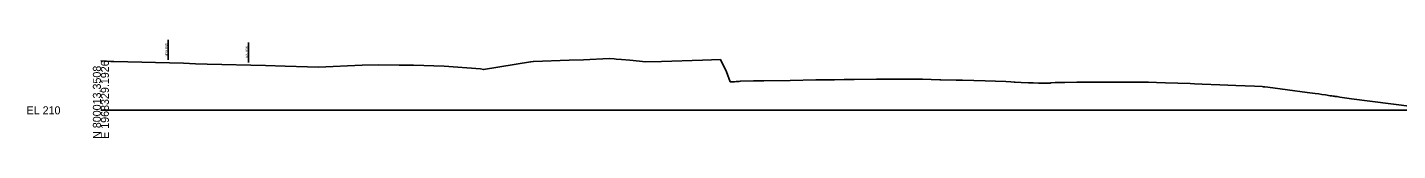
# Model space of a CAD drawing. Extents: x 1979833 to 1982361, y 790388 to 810009.
# Drawn here: x 1979832.9 to 1980312.1, y 802388 to 802422.3 of the extents above; entities that cross this region are included whole.
import ezdxf

# ---------------------------------------------------------------- set-up
doc = ezdxf.new("R2010")
doc.units = 0
for name, color, linetype in [('Default', 7, 'Continuous'), ('RD_GPK_XS_Cell', 7, 'Continuous'), ('RD_XS_ExGround', 7, 'Continuous'), ('RD_XS_ExRW', 7, 'Continuous'), ('RD_XS_NewRW', 7, 'Continuous')]:
    doc.layers.add(name, color=color, linetype=linetype)

msp = doc.modelspace()

# ---------------------------------------------------------------- linework, layer by layer
at = {"layer": 'RD_GPK_XS_Cell'}
msp.add_line((1979858.57, 802397.73), (1980358.57, 802397.73), dxfattribs=at)
at = {"layer": 'RD_XS_ExGround'}
msp.add_lwpolyline([(1979858.57, 802415.01), (1979860.53, 802414.89), (1979862.08, 802414.85), (1979863.05, 802414.85), (1979887.48, 802414.21), (1979891.72, 802414.04), (1979895.79, 802413.86), (1979916.1, 802413.39), (1979923, 802413.2), (1979930.84, 802412.99), (1979934.73, 802412.85), (1979950.02, 802413.53), (1979955.64, 802413.65), (1979962.96, 802413.58), (1979967.94, 802413.57), (1979978.62, 802413.24), (1979991.39, 802412.21), (1979992.39, 802411.99), (1980008.88, 802414.69), (1980009.85, 802414.86), (1980022.36, 802415.25), (1980027.44, 802415.44), (1980036.41, 802415.83), (1980038.15, 802415.7), (1980038.79, 802415.66), (1980040.63, 802415.51), (1980043.57, 802415.31), (1980049.18, 802414.7), (1980054.71, 802414.81), (1980069.06, 802415.34), (1980075.25, 802415.55), (1980077.42, 802411.21), (1980078.7, 802407.74), (1980079.39, 802407.75), (1980080.26, 802407.76), (1980080.8, 802407.79), (1980081.83, 802407.86), (1980082.26, 802407.95), (1980086.84, 802408.02), (1980089.16, 802408.07), (1980090.42, 802408.08), (1980099.68, 802408.22), (1980108.71, 802408.36), (1980111.25, 802408.39), (1980115.19, 802408.46), (1980118.54, 802408.49), (1980122.07, 802408.54), (1980129.84, 802408.63), (1980131.72, 802408.63), (1980136.83, 802408.64), (1980139.34, 802408.65), (1980142.44, 802408.63), (1980144.26, 802408.62), (1980144.73, 802408.63), (1980145.14, 802408.64), (1980145.96, 802408.61), (1980151.99, 802408.46), (1980152.42, 802408.45), (1980157.73, 802408.32), (1980160, 802408.26), (1980167.86, 802408.01), (1980175.09, 802407.77), (1980176.83, 802407.69), (1980178.08, 802407.63), (1980178.4, 802407.55), (1980180.47, 802407.46), (1980183.08, 802407.37), (1980184.73, 802407.33), (1980186.53, 802407.29), (1980187.77, 802407.29), (1980190.6, 802407.29), (1980190.86, 802407.41), (1980192.42, 802407.45), (1980194.48, 802407.5), (1980195.77, 802407.51), (1980199.96, 802407.54), (1980206.37, 802407.59), (1980209.12, 802407.62), (1980212.61, 802407.61), (1980216.33, 802407.6), (1980218.55, 802407.59), (1980224.31, 802407.57), (1980225.01, 802407.54), (1980227.77, 802407.44), (1980230.96, 802407.34), (1980239.53, 802407.09), (1980241.07, 802407.02), (1980243.82, 802406.9), (1980250.02, 802406.65), (1980255.54, 802406.41), (1980262.06, 802406.16), (1980264.72, 802406.07), (1980265.23, 802405.94), (1980265.66, 802405.92), (1980266.81, 802405.86), (1980280.54, 802403.96), (1980283.35, 802403.6), (1980284.63, 802403.45), (1980285.63, 802403.29), (1980286.93, 802403.1), (1980288.61, 802402.85), (1980289.11, 802402.77), (1980289.59, 802402.71), (1980289.97, 802402.66), (1980290.3, 802402.61), (1980290.97, 802402.53), (1980291.97, 802402.38), (1980296.04, 802401.79), (1980317.16, 802399.05)], dxfattribs=at)
at = {"layer": 'RD_XS_ExRW'}
msp.add_line((1979910.23, 802414.52), (1979910.23, 802421.52), dxfattribs=at)
at = {"layer": 'RD_XS_NewRW'}
msp.add_line((1979882.15, 802415.35), (1979882.15, 802422.35), dxfattribs=at)

# ---------------------------------------------------------------- texts
at = {"layer": 'Default'}
msp.add_text('-', height=0.0001, dxfattribs=at).set_placement((1979858.57, 802397.73))
at = {"layer": 'RD_GPK_XS_Cell'}
for s, p in [('N 800013.3508', (1979858.57, 802387.73)), ('E 1968329.1926', (1979861.37, 802387.73))]:
    msp.add_text(s, height=2.8, rotation=90, dxfattribs=at).set_placement(p)
msp.add_text('EL 210', height=2.8, dxfattribs=at).set_placement((1979832.57, 802396.33))
at = {"layer": 'RD_XS_ExRW'}
msp.add_text('EX. R/W ', height=0.75, rotation=90, dxfattribs=at).set_placement((1979909.92, 802416.21))
at = {"layer": 'RD_XS_NewRW'}
msp.add_text('NEW R/W ', height=0.75, rotation=90, dxfattribs=at).set_placement((1979881.85, 802416.49))

doc.saveas('drawing.dxf')
